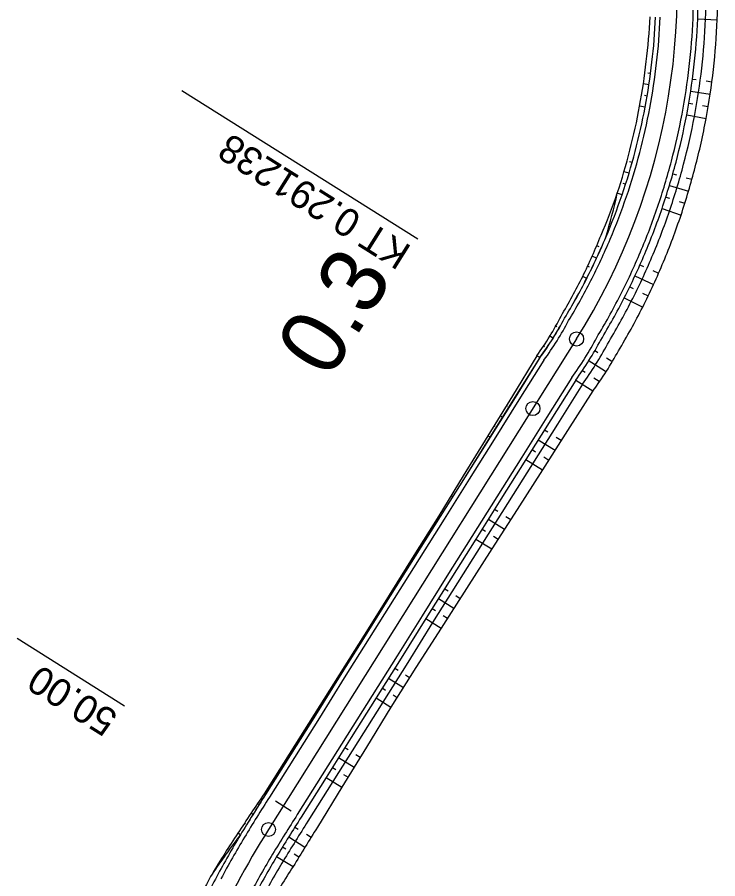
# Model space of a CAD drawing. Extents: x -481656 to -478728, y -1113199 to -1110710.
# Drawn here: x -479592.8 to -479518.1, y -1112691.1 to -1112599.2 of the extents above; entities that cross this region are included whole.
import ezdxf

# ---------------------------------------------------------------- set-up
doc = ezdxf.new("R2010")
doc.units = 0
for name, color, linetype in [('C1_HATCH_SLOPE_L', 7, 'Continuous'), ('C1_HATCH_SLOPE_R', 7, 'Continuous'), ('C1_HECTOMETRY', 7, 'Continuous'), ('C1_HLBODY', 7, 'Continuous'), ('C1_HRANA_TELESO', 7, 'Continuous'), ('C1_KORUNA', 7, 'Continuous'), ('C1_OSA', 7, 'Continuous'), ('C1_PRIKOP', 7, 'Continuous'), ('C1_STANICENI', 7, 'Continuous'), ('C1_VOZOVKA', 7, 'Continuous'), ('C1_ZPEVKRAJ', 7, 'Continuous')]:
    doc.layers.add(name, color=color, linetype=linetype)

msp = doc.modelspace()

# ---------------------------------------------------------------- linework, layer by layer
at = {"layer": 'C1_HATCH_SLOPE_L'}
for p, q in [((-479520.282, -1112599.413), (-479518.205, -1112599.503)), ((-479520.848, -1112605.837), (-479520.433, -1112605.892)), ((-479519.391, -1112606.031), (-479518.764, -1112606.115)), ((-479521.03, -1112607.114), (-479518.95, -1112607.429)), ((-479521.235, -1112608.388), (-479520.822, -1112608.458)), ((-479519.784, -1112608.634), (-479519.159, -1112608.741)), ((-479521.463, -1112609.658), (-479519.391, -1112610.048)), ((-479522.938, -1112615.935), (-479522.535, -1112616.049)), ((-479521.514, -1112616.338), (-479520.896, -1112616.513)), ((-479523.3, -1112617.174), (-479521.263, -1112617.789)), ((-479523.684, -1112618.405), (-479523.286, -1112618.534)), ((-479522.27, -1112618.86), (-479521.652, -1112619.059)), ((-479524.09, -1112619.63), (-479522.065, -1112620.322)), ((-479526.444, -1112625.634), (-479526.061, -1112625.804)), ((-479526.978, -1112626.808), (-479524.996, -1112627.732)), ((-479525.065, -1112626.246), (-479524.452, -1112626.519)), ((-479527.534, -1112627.973), (-479527.158, -1112628.156)), ((-479526.171, -1112628.638), (-479525.561, -1112628.935)), ((-479528.11, -1112629.127), (-479526.147, -1112630.129)), ((-479531.295, -1112634.734), (-479530.94, -1112634.957)), ((-479531.96, -1112635.792), (-479530.104, -1112636.958)), ((-479530.008, -1112635.543), (-479529.43, -1112635.906)), ((-479532.625, -1112636.851), (-479532.27, -1112637.074)), ((-479533.29, -1112637.909), (-479531.452, -1112639.064)), ((-479531.347, -1112637.654), (-479530.778, -1112638.011)), ((-479536.615, -1112643.201), (-479536.26, -1112643.424)), ((-479537.28, -1112644.26), (-479535.497, -1112645.38)), ((-479535.364, -1112643.987), (-479534.823, -1112644.327)), ((-479537.945, -1112645.318), (-479537.59, -1112645.541)), ((-479538.61, -1112646.377), (-479536.846, -1112647.485)), ((-479536.704, -1112646.098), (-479536.172, -1112646.432)), ((-479541.935, -1112651.669), (-479541.58, -1112651.892)), ((-479542.6, -1112652.727), (-479540.891, -1112653.801)), ((-479540.722, -1112652.431), (-479540.217, -1112652.748)), ((-479543.265, -1112653.785), (-479542.91, -1112654.008)), ((-479542.06, -1112654.542), (-479541.564, -1112654.854)), ((-479543.93, -1112654.844), (-479542.238, -1112655.907)), ((-479547.256, -1112660.136), (-479546.901, -1112660.358)), ((-479546.078, -1112660.876), (-479545.61, -1112661.17)), ((-479547.921, -1112661.194), (-479546.284, -1112662.223)), ((-479548.586, -1112662.253), (-479548.231, -1112662.476)), ((-479549.251, -1112663.311), (-479547.632, -1112664.328)), ((-479547.417, -1112662.986), (-479546.958, -1112663.275)), ((-479552.576, -1112668.603), (-479552.222, -1112668.826)), ((-479551.43, -1112669.324), (-479550.992, -1112669.598)), ((-479553.241, -1112669.662), (-479551.655, -1112670.658)), ((-479553.906, -1112670.72), (-479553.552, -1112670.943)), ((-479554.571, -1112671.778), (-479552.981, -1112672.777)), ((-479552.758, -1112671.442), (-479552.318, -1112671.718)), ((-479557.896, -1112677.07), (-479557.542, -1112677.293)), ((-479558.561, -1112678.129), (-479556.905, -1112679.169)), ((-479556.719, -1112677.81), (-479556.251, -1112678.104)), ((-479559.226, -1112679.187), (-479558.872, -1112679.41)), ((-479559.891, -1112680.246), (-479558.213, -1112681.3)), ((-479558.038, -1112679.934), (-479557.559, -1112680.235)), ((-479563.216, -1112685.538), (-479562.862, -1112685.76)), ((-479563.881, -1112686.596), (-479562.147, -1112687.686)), ((-479561.997, -1112686.304), (-479561.487, -1112686.624)), ((-479564.535, -1112687.641), (-479564.178, -1112687.861)), ((-479563.304, -1112688.4), (-479562.787, -1112688.72)), ((-479565.17, -1112688.685), (-479563.405, -1112689.745))]:
    msp.add_line(p, q, dxfattribs=at)
at = {"layer": 'C1_HATCH_SLOPE_R'}
for p, q in [((-479525.917, -1112605.161), (-479525.917, -1112605.161)), ((-479525.309, -1112605.242), (-479525.613, -1112605.202)), ((-479525.48, -1112606.439), (-479526.082, -1112606.348)), ((-479526.268, -1112607.533), (-479526.268, -1112607.533)), ((-479525.672, -1112607.634), (-479525.97, -1112607.584)), ((-479525.885, -1112608.825), (-479526.476, -1112608.714)), ((-479527.819, -1112614.556), (-479527.819, -1112614.556)), ((-479527.268, -1112614.712), (-479527.544, -1112614.634)), ((-479527.608, -1112615.873), (-479528.144, -1112615.711)), ((-479528.489, -1112616.86), (-479528.489, -1112616.86)), ((-479527.968, -1112617.028), (-479528.228, -1112616.944)), ((-479528.349, -1112618.176), (-479528.855, -1112618.003)), ((-479530.806, -1112623.694), (-479531.048, -1112623.587)), ((-479530.556, -1112623.806), (-479530.561, -1112623.804)), ((-479531.057, -1112624.907), (-479531.528, -1112624.688)), ((-479531.807, -1112625.888), (-479532.027, -1112625.78)), ((-479531.578, -1112625.999), (-479531.582, -1112625.997)), ((-479532.118, -1112627.081), (-479532.546, -1112626.863)), ((-479535.288, -1112632.225), (-479535.463, -1112632.115)), ((-479535.105, -1112632.34), (-479535.109, -1112632.338)), ((-479535.77, -1112633.398), (-479536.117, -1112633.18)), ((-479536.607, -1112634.348), (-479536.77, -1112634.246)), ((-479536.435, -1112634.457), (-479536.44, -1112634.454)), ((-479537.1, -1112635.515), (-479537.424, -1112635.311)), ((-479540.564, -1112640.72), (-479540.693, -1112640.639)), ((-479540.425, -1112640.807), (-479540.429, -1112640.804)), ((-479541.09, -1112641.866), (-479541.347, -1112641.704)), ((-479541.882, -1112642.844), (-479542.001, -1112642.77)), ((-479541.755, -1112642.924), (-479541.76, -1112642.922)), ((-479542.42, -1112643.982), (-479542.655, -1112643.835)), ((-479545.839, -1112649.216), (-479545.924, -1112649.162)), ((-479545.746, -1112649.274), (-479545.75, -1112649.272)), ((-479546.411, -1112650.333), (-479546.578, -1112650.228)), ((-479547.158, -1112651.34), (-479547.232, -1112651.293)), ((-479547.076, -1112651.391), (-479547.08, -1112651.388)), ((-479547.741, -1112652.45), (-479547.886, -1112652.359)), ((-479551.136, -1112657.698), (-479551.197, -1112657.66)), ((-479551.066, -1112657.742), (-479551.07, -1112657.739)), ((-479551.731, -1112658.8), (-479551.859, -1112658.72)), ((-479552.462, -1112659.816), (-479552.521, -1112659.78)), ((-479552.396, -1112659.859), (-479552.4, -1112659.856)), ((-479553.061, -1112660.917), (-479553.183, -1112660.84)), ((-479556.449, -1112666.17), (-479556.503, -1112666.136)), ((-479556.386, -1112666.209), (-479556.39, -1112666.206)), ((-479557.051, -1112667.267), (-479557.169, -1112667.193)), ((-479557.78, -1112668.286), (-479557.836, -1112668.251)), ((-479557.716, -1112668.326), (-479557.72, -1112668.323)), ((-479558.381, -1112669.384), (-479558.502, -1112669.308)), ((-479561.778, -1112674.632), (-479561.84, -1112674.592)), ((-479561.706, -1112674.676), (-479561.71, -1112674.674)), ((-479562.371, -1112675.735), (-479562.508, -1112675.649)), ((-479563.11, -1112676.747), (-479563.176, -1112676.706)), ((-479563.036, -1112676.793), (-479563.04, -1112676.79)), ((-479563.701, -1112677.851), (-479563.843, -1112677.762)), ((-479567.121, -1112683.084), (-479567.207, -1112683.03)), ((-479567.027, -1112683.144), (-479567.031, -1112683.141)), ((-479567.692, -1112684.202), (-479567.901, -1112684.07)), ((-479568.488, -1112685.2), (-479568.604, -1112685.128)), ((-479568.363, -1112685.277), (-479568.368, -1112685.274)), ((-479569.028, -1112686.368), (-479569.301, -1112686.205))]:
    msp.add_line(p, q, dxfattribs=at)
at = {"layer": 'C1_HECTOMETRY'}
msp.add_circle((-479537.855, -1112640.946), 0.75, dxfattribs=at)
at = {"layer": 'C1_HLBODY'}
msp.add_line((-479550.128, -1112622.886), (-479575.276, -1112607.085), dxfattribs=at)
for centre in [(-479533.193, -1112633.527), (-479566.038, -1112685.8)]:
    msp.add_circle(centre, 0.75, dxfattribs=at)
at = {"layer": 'C1_HRANA_TELESO'}
for p, q in [((-479537.424, -1112635.311), (-479540.039, -1112639.573)), ((-479531.452, -1112639.064), (-479534.149, -1112643.274)), ((-479540.039, -1112639.573), (-479542.655, -1112643.835)), ((-479534.149, -1112643.274), (-479536.846, -1112647.485)), ((-479542.655, -1112643.835), (-479545.271, -1112648.097)), ((-479545.271, -1112648.097), (-479547.886, -1112652.359)), ((-479536.846, -1112647.485), (-479539.543, -1112651.695)), ((-479539.543, -1112651.695), (-479542.238, -1112655.907)), ((-479547.886, -1112652.359), (-479550.534, -1112656.599)), ((-479542.238, -1112655.907), (-479544.935, -1112660.117)), ((-479550.534, -1112656.599), (-479553.183, -1112660.84)), ((-479544.935, -1112660.117), (-479547.632, -1112664.328)), ((-479553.183, -1112660.84), (-479555.836, -1112665.078)), ((-479547.632, -1112664.328), (-479550.329, -1112668.538)), ((-479555.836, -1112665.078), (-479558.502, -1112669.308)), ((-479558.502, -1112669.308), (-479561.173, -1112673.535)), ((-479550.329, -1112668.538), (-479552.981, -1112672.777)), ((-479552.981, -1112672.777), (-479555.597, -1112677.039)), ((-479561.173, -1112673.535), (-479563.843, -1112677.762)), ((-479555.597, -1112677.039), (-479558.213, -1112681.3)), ((-479563.843, -1112677.762), (-479566.512, -1112681.991)), ((-479558.213, -1112681.3), (-479560.826, -1112685.563))]:
    msp.add_line(p, q, dxfattribs=at)
for centre, radius, start, end in [((-479592.466, -1112596.575), 74.319, 357.74239, 1.83497), ((-479592.427, -1112595.835), 67.149, 353.04074, 357.13339), ((-479592.487, -1112596.585), 74.34, 353.65807, 357.75066), ((-479592.498, -1112596.511), 67.141, 349.52848, 353.62106), ((-479592.48, -1112596.386), 74.354, 349.41261, 353.50517), ((-479592.514, -1112596.506), 67.157, 345.43424, 349.52682), ((-479592.49, -1112596.399), 74.362, 345.33132, 349.42389), ((-479592.664, -1112596.958), 67.19, 341.74696, 345.83974), ((-479592.559, -1112596.599), 74.378, 341.40125, 345.49385), ((-479592.345, -1112595.973), 67.203, 336.77158, 340.86419), ((-479592.623, -1112596.703), 74.406, 337.4, 341.49263), ((-479592.92, -1112597.283), 67.231, 333.89718, 337.99028), ((-479592.651, -1112596.687), 74.438, 333.30448, 337.39711), ((-479592.763, -1112596.828), 67.292, 329.39779, 333.49052), ((-479592.528, -1112596.4), 74.458, 328.97207, 333.06463), ((-479564.782, -1112615.706), 33.657, 324.37327, 332.81233), ((-479561.419, -1112616.969), 37.231, 323.59814, 331.42023), ((-479311.308, -1112853.899), 307.703, 146.03535, 146.97631), ((-479317.766, -1112838.312), 287.073, 147.85302, 148.83354), ((-479484.027, -1112743.434), 102.697, 146.13362, 149.00204), ((-479483.185, -1112742.076), 95.78, 146.88158, 149.74836), ((-479481.642, -1112739.549), 102.842, 151.54244, 154.40728)]:
    msp.add_arc(centre, radius, start, end, dxfattribs=at)
at = {"layer": 'C1_KORUNA'}
for p, q in [((-479537.1, -1112635.515), (-479539.76, -1112639.749)), ((-479533.29, -1112637.909), (-479535.95, -1112642.143)), ((-479539.76, -1112639.749), (-479542.42, -1112643.982)), ((-479535.95, -1112642.143), (-479538.61, -1112646.377)), ((-479542.42, -1112643.982), (-479545.08, -1112648.216)), ((-479538.61, -1112646.377), (-479541.27, -1112650.61)), ((-479545.08, -1112648.216), (-479547.741, -1112652.45)), ((-479541.27, -1112650.61), (-479543.93, -1112654.844)), ((-479547.741, -1112652.45), (-479550.401, -1112656.683)), ((-479543.93, -1112654.844), (-479546.59, -1112659.077)), ((-479550.401, -1112656.683), (-479553.061, -1112660.917)), ((-479546.59, -1112659.077), (-479549.251, -1112663.311)), ((-479553.061, -1112660.917), (-479555.721, -1112665.151)), ((-479549.251, -1112663.311), (-479551.911, -1112667.545)), ((-479555.721, -1112665.151), (-479558.381, -1112669.384)), ((-479551.911, -1112667.545), (-479554.571, -1112671.778)), ((-479558.381, -1112669.384), (-479561.041, -1112673.618)), ((-479554.571, -1112671.778), (-479557.231, -1112676.012)), ((-479561.041, -1112673.618), (-479563.701, -1112677.851)), ((-479557.231, -1112676.012), (-479559.891, -1112680.246)), ((-479563.701, -1112677.851), (-479566.362, -1112682.085)), ((-479559.891, -1112680.246), (-479562.551, -1112684.479))]:
    msp.add_line(p, q, dxfattribs=at)
for centre, radius, start, end in [((-479592.464, -1112596.285), 72.25, 357.51853, 1.61109), ((-479592.464, -1112596.285), 67.75, 353.42598, 357.51853), ((-479592.464, -1112596.285), 72.25, 353.42598, 357.51853), ((-479592.464, -1112596.285), 67.75, 349.33342, 353.42598), ((-479592.464, -1112596.285), 72.25, 349.33342, 353.42598), ((-479592.464, -1112596.285), 67.75, 345.24086, 349.33342), ((-479592.464, -1112596.285), 72.25, 345.24087, 349.33342), ((-479592.464, -1112596.285), 67.75, 341.14831, 345.24086), ((-479592.464, -1112596.285), 72.25, 341.14831, 345.24087), ((-479592.464, -1112596.285), 67.75, 337.05575, 341.14831), ((-479592.464, -1112596.285), 72.25, 337.05576, 341.14831), ((-479592.464, -1112596.285), 67.75, 332.9632, 337.05575), ((-479592.464, -1112596.285), 72.25, 332.9632, 337.05576), ((-479592.464, -1112596.285), 67.75, 328.87064, 332.9632), ((-479592.464, -1112596.285), 72.25, 328.87064, 332.9632), ((-479564.429, -1112615.499), 33.875, 323.78125, 332.17832), ((-479562.51, -1112616.668), 36.125, 323.98599, 331.98571), ((-479307.293, -1112846.338), 306.75, 147.62477, 148.5672), ((-479314.937, -1112841.586), 293.25, 147.60569, 148.57368), ((-479481.366, -1112739.002), 102.25, 149.01874, 151.88353), ((-479481.366, -1112739.002), 97.75, 149.01874, 151.88353), ((-479481.366, -1112739.002), 102.25, 151.88353, 154.74832)]:
    msp.add_arc(centre, radius, start, end, dxfattribs=at)
at = {"layer": 'C1_OSA'}
msp.add_line((-479533.193, -1112633.527), (-479566.038, -1112685.8), dxfattribs=at)
for centre, radius, start, end in [((-479592.464, -1112596.285), 70, 327.85751, 13.42691), ((-479481.366, -1112739.002), 100, 147.85753, 163.12732)]:
    msp.add_arc(centre, radius, start, end, dxfattribs=at)
at = {"layer": 'C1_PRIKOP'}
for p, q in [((-479537.109, -1112635.51), (-479539.769, -1112639.743)), ((-479532.581, -1112638.355), (-479535.241, -1112642.589)), ((-479539.769, -1112639.743), (-479542.429, -1112643.977)), ((-479535.241, -1112642.589), (-479537.901, -1112646.822)), ((-479542.429, -1112643.977), (-479545.089, -1112648.211)), ((-479537.901, -1112646.822), (-479540.561, -1112651.056)), ((-479545.089, -1112648.211), (-479547.749, -1112652.444)), ((-479540.561, -1112651.056), (-479543.221, -1112655.289)), ((-479547.749, -1112652.444), (-479550.409, -1112656.678)), ((-479543.221, -1112655.289), (-479545.881, -1112659.523)), ((-479550.409, -1112656.678), (-479553.069, -1112660.912)), ((-479545.881, -1112659.523), (-479548.541, -1112663.757)), ((-479553.069, -1112660.912), (-479555.729, -1112665.145)), ((-479548.541, -1112663.757), (-479551.201, -1112667.99)), ((-479555.729, -1112665.145), (-479558.39, -1112669.379)), ((-479551.201, -1112667.99), (-479553.862, -1112672.224)), ((-479558.39, -1112669.379), (-479561.05, -1112673.613)), ((-479553.862, -1112672.224), (-479556.522, -1112676.458)), ((-479561.05, -1112673.613), (-479563.71, -1112677.846)), ((-479556.522, -1112676.458), (-479559.182, -1112680.691)), ((-479563.71, -1112677.846), (-479566.37, -1112682.08)), ((-479559.182, -1112680.691), (-479561.842, -1112684.925))]:
    msp.add_line(p, q, dxfattribs=at)
for centre, radius, start, end in [((-479592.464, -1112596.285), 73.088, 357.51854, 1.61109), ((-479592.464, -1112596.285), 73.088, 353.42598, 357.51854), ((-479592.464, -1112596.285), 73.088, 349.33343, 353.42598), ((-479592.464, -1112596.285), 73.088, 345.24087, 349.33343), ((-479592.464, -1112596.285), 73.088, 341.14831, 345.24087), ((-479594.699, -1112603.25), 67.478, 343.25369, 347.37042), ((-479592.464, -1112596.285), 73.088, 337.05576, 341.14831), ((-479592.464, -1112596.285), 67.74, 332.9632, 337.05575), ((-479592.464, -1112596.285), 73.088, 332.9632, 337.05576), ((-479592.464, -1112596.285), 67.74, 328.87064, 332.96319), ((-479592.464, -1112596.285), 73.088, 328.87065, 332.9632), ((-479564.434, -1112615.497), 33.87, 323.78077, 332.17878), ((-479562.153, -1112616.886), 36.544, 324.02138, 331.95254), ((-479307.276, -1112846.349), 306.78, 147.62481, 148.56718), ((-479316.359, -1112840.701), 290.737, 147.60198, 148.57499), ((-479487.459, -1112748.494), 102.543, 142.70623, 145.58845), ((-479481.366, -1112739.002), 96.912, 149.01874, 151.88353)]:
    msp.add_arc(centre, radius, start, end, dxfattribs=at)
at = {"layer": 'C1_STANICENI'}
for p, q in [((-479581.391, -1112672.642), (-479592.822, -1112665.459)), ((-479565.303, -1112682.75), (-479563.61, -1112683.814))]:
    msp.add_line(p, q, dxfattribs=at)
at = {"layer": 'C1_VOZOVKA'}
for p, q in [((-479536.677, -1112635.781), (-479539.337, -1112640.015)), ((-479533.713, -1112637.643), (-479536.373, -1112641.877)), ((-479539.337, -1112640.015), (-479541.997, -1112644.248)), ((-479536.373, -1112641.877), (-479539.033, -1112646.11)), ((-479541.997, -1112644.248), (-479544.657, -1112648.482)), ((-479539.033, -1112646.11), (-479541.694, -1112650.344)), ((-479544.657, -1112648.482), (-479547.317, -1112652.716)), ((-479541.694, -1112650.344), (-479544.354, -1112654.578)), ((-479547.317, -1112652.716), (-479549.977, -1112656.949)), ((-479544.354, -1112654.578), (-479547.014, -1112658.811)), ((-479549.977, -1112656.949), (-479552.638, -1112661.183)), ((-479547.014, -1112658.811), (-479549.674, -1112663.045)), ((-479552.638, -1112661.183), (-479555.298, -1112665.417)), ((-479549.674, -1112663.045), (-479552.334, -1112667.279)), ((-479555.298, -1112665.417), (-479557.958, -1112669.65)), ((-479552.334, -1112667.279), (-479554.994, -1112671.512)), ((-479557.958, -1112669.65), (-479560.618, -1112673.884)), ((-479554.994, -1112671.512), (-479557.654, -1112675.746)), ((-479560.618, -1112673.884), (-479563.278, -1112678.118)), ((-479557.654, -1112675.746), (-479560.314, -1112679.98)), ((-479563.278, -1112678.118), (-479565.938, -1112682.351)), ((-479560.314, -1112679.98), (-479562.975, -1112684.213))]:
    msp.add_line(p, q, dxfattribs=at)
for centre, radius, start, end in [((-479592.464, -1112596.285), 71.75, 357.51853, 1.61109), ((-479592.464, -1112596.285), 68.25, 353.42598, 357.51853), ((-479592.464, -1112596.285), 71.75, 353.42598, 357.51853), ((-479592.464, -1112596.285), 68.25, 349.33342, 353.42598), ((-479592.464, -1112596.285), 71.75, 349.33342, 353.42598), ((-479592.464, -1112596.285), 68.25, 345.24086, 349.33342), ((-479592.464, -1112596.285), 71.75, 345.24087, 349.33342), ((-479592.464, -1112596.285), 68.25, 341.14831, 345.24086), ((-479592.464, -1112596.285), 71.75, 341.14831, 345.24087), ((-479592.464, -1112596.285), 68.25, 337.05575, 341.14831), ((-479592.464, -1112596.285), 71.75, 337.05576, 341.14831), ((-479592.464, -1112596.285), 68.25, 332.9632, 337.05575), ((-479592.464, -1112596.285), 71.75, 332.9632, 337.05576), ((-479592.464, -1112596.285), 68.25, 328.87064, 332.9632), ((-479592.464, -1112596.285), 71.75, 328.87064, 332.9632), ((-479564.216, -1112615.629), 34.125, 323.80531, 332.15563), ((-479562.724, -1112616.538), 35.875, 323.96449, 332.00589), ((-479308.142, -1112845.81), 305.25, 147.62272, 148.56787), ((-479314.087, -1112842.114), 294.75, 147.60788, 148.57291), ((-479481.366, -1112739.002), 101.75, 149.01874, 151.88353), ((-479481.366, -1112739.002), 98.25, 149.01874, 151.88353)]:
    msp.add_arc(centre, radius, start, end, dxfattribs=at)
at = {"layer": 'C1_ZPEVKRAJ'}
for p, q in [((-479536.677, -1112635.781), (-479539.337, -1112640.015)), ((-479533.713, -1112637.643), (-479536.373, -1112641.877)), ((-479539.337, -1112640.015), (-479541.997, -1112644.248)), ((-479536.373, -1112641.877), (-479539.033, -1112646.11)), ((-479541.997, -1112644.248), (-479544.657, -1112648.482)), ((-479539.033, -1112646.11), (-479541.694, -1112650.344)), ((-479544.657, -1112648.482), (-479547.317, -1112652.716)), ((-479541.694, -1112650.344), (-479544.354, -1112654.578)), ((-479547.317, -1112652.716), (-479549.977, -1112656.949)), ((-479544.354, -1112654.578), (-479547.014, -1112658.811)), ((-479549.977, -1112656.949), (-479552.638, -1112661.183)), ((-479547.014, -1112658.811), (-479549.674, -1112663.045)), ((-479552.638, -1112661.183), (-479555.298, -1112665.417)), ((-479549.674, -1112663.045), (-479552.334, -1112667.279)), ((-479555.298, -1112665.417), (-479557.958, -1112669.65)), ((-479552.334, -1112667.279), (-479554.994, -1112671.512)), ((-479557.958, -1112669.65), (-479560.618, -1112673.884)), ((-479554.994, -1112671.512), (-479557.654, -1112675.746)), ((-479560.618, -1112673.884), (-479563.278, -1112678.118)), ((-479557.654, -1112675.746), (-479560.314, -1112679.98)), ((-479563.278, -1112678.118), (-479565.938, -1112682.351)), ((-479560.314, -1112679.98), (-479562.975, -1112684.213))]:
    msp.add_line(p, q, dxfattribs=at)
for centre, radius, start, end in [((-479592.464, -1112596.285), 71.75, 357.51853, 1.61109), ((-479592.464, -1112596.285), 68.25, 353.42598, 357.51853), ((-479592.464, -1112596.285), 71.75, 353.42598, 357.51853), ((-479592.464, -1112596.285), 68.25, 349.33342, 353.42598), ((-479592.464, -1112596.285), 71.75, 349.33342, 353.42598), ((-479592.464, -1112596.285), 68.25, 345.24086, 349.33342), ((-479592.464, -1112596.285), 71.75, 345.24087, 349.33342), ((-479592.464, -1112596.285), 68.25, 341.14831, 345.24086), ((-479592.464, -1112596.285), 71.75, 341.14831, 345.24087), ((-479592.464, -1112596.285), 68.25, 337.05575, 341.14831), ((-479592.464, -1112596.285), 71.75, 337.05576, 341.14831), ((-479592.464, -1112596.285), 68.25, 332.9632, 337.05575), ((-479592.464, -1112596.285), 71.75, 332.9632, 337.05576), ((-479592.464, -1112596.285), 68.25, 328.87064, 332.9632), ((-479592.464, -1112596.285), 71.75, 328.87064, 332.9632), ((-479564.216, -1112615.629), 34.125, 323.80531, 332.15563), ((-479562.724, -1112616.538), 35.875, 323.96449, 332.00589), ((-479308.142, -1112845.81), 305.25, 147.62272, 148.56787), ((-479314.087, -1112842.114), 294.75, 147.60788, 148.57291), ((-479481.366, -1112739.002), 101.75, 149.01874, 151.88353), ((-479481.366, -1112739.002), 98.25, 149.01874, 151.88353)]:
    msp.add_arc(centre, radius, start, end, dxfattribs=at)

# ---------------------------------------------------------------- texts
at = {"layer": 'C1_HECTOMETRY'}
msp.add_text('0.3', height=7, rotation=57.81189, dxfattribs=at).set_placement((-479559.606, -1112637.958))
at = {"layer": 'C1_HLBODY'}
msp.add_text('KT 0.291238', height=3, rotation=147.85752, dxfattribs=at).set_placement((-479550.659, -1112623.733))
at = {"layer": 'C1_STANICENI'}
msp.add_text('50.00', height=3, rotation=147.85752, dxfattribs=at).set_placement((-479581.922, -1112673.489))

doc.saveas('drawing.dxf')
